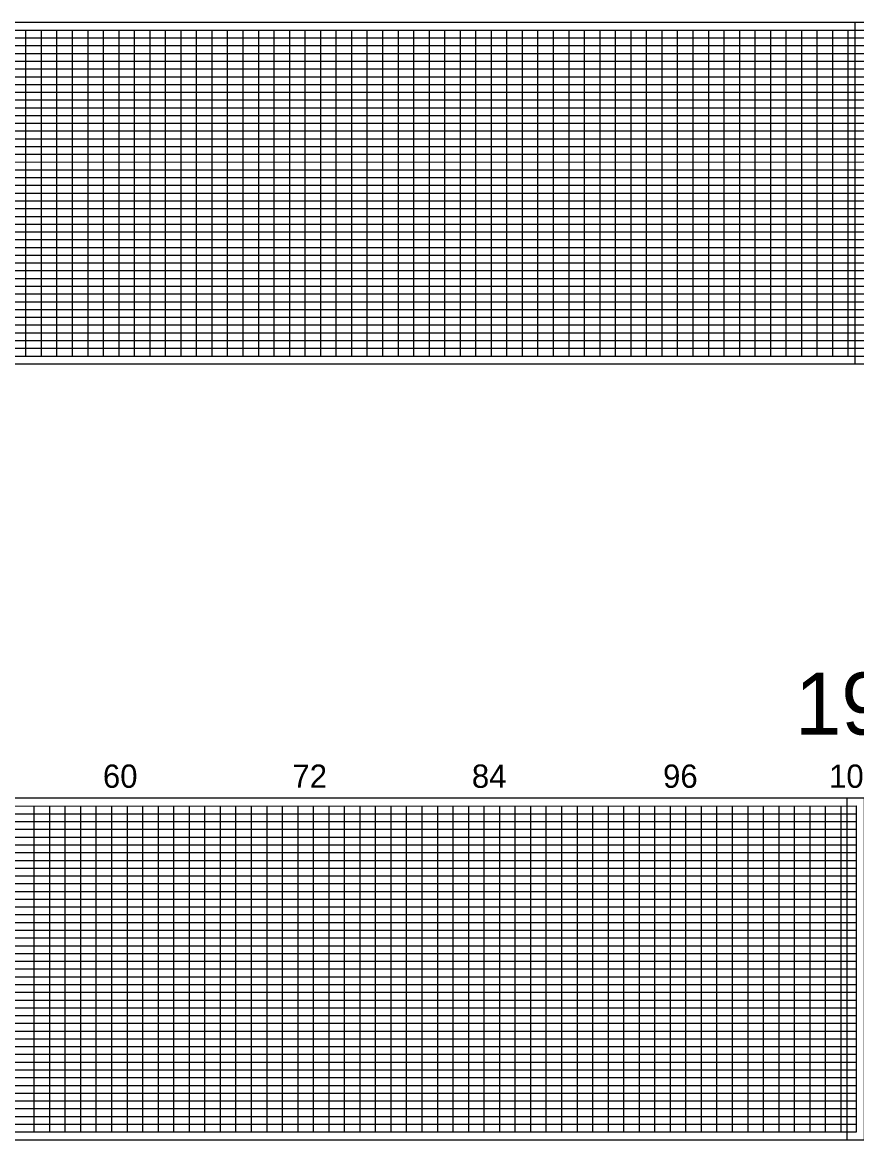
# Model space of a CAD drawing. Extents: x 1914168 to 1925341, y 720939 to 777401.
# Drawn here: x 1917143 to 1919832, y 735939 to 739539 of the extents above; entities that cross this region are included whole.
import ezdxf

# ---------------------------------------------------------------- set-up
doc = ezdxf.new("R2010")
doc.units = 0
for name, color, linetype in [('RD_PD_ALT1_CL', 7, 'Continuous'), ('RD_PD_WallFill', 7, 'Continuous'), ('RD_SHT_IplotShp', 7, 'Continuous')]:
    doc.layers.add(name, color=color, linetype=linetype)

msp = doc.modelspace()

# ---------------------------------------------------------------- linework, layer by layer
at = {"layer": 'RD_PD_WallFill'}
for p, q in [((1914504.9, 739514.1), (1919854.9, 739514.2)), ((1917154.9, 738464.2), (1917154.9, 739514.2)), ((1917204.9, 738464.2), (1917204.9, 739514.2)), ((1917254.9, 738464.2), (1917254.9, 739514.2)), ((1917304.9, 738464.2), (1917304.9, 739514.2)), ((1917354.9, 738464.2), (1917354.9, 739514.2)), ((1917404.9, 738464.2), (1917404.9, 739514.2)), ((1917454.9, 738464.2), (1917454.9, 739514.2)), ((1917504.9, 738464.2), (1917504.9, 739514.2)), ((1917554.9, 738464.2), (1917554.9, 739514.2)), ((1917604.9, 738464.1), (1917604.9, 739514.2)), ((1917654.9, 738464.2), (1917654.9, 739514.2)), ((1917704.9, 738464.2), (1917704.9, 739514.2)), ((1917754.9, 738464.2), (1917754.9, 739514.2)), ((1917804.9, 738464.2), (1917804.9, 739514.2)), ((1917854.9, 738464.2), (1917854.9, 739514.2)), ((1917904.9, 738464.1), (1917904.9, 739514.2)), ((1917954.9, 738464.1), (1917954.9, 739514.2)), ((1918004.9, 738464.2), (1918004.9, 739514.2)), ((1918054.9, 738464.2), (1918054.9, 739514.2)), ((1918104.9, 738464.2), (1918104.9, 739514.2)), ((1918154.9, 738464.2), (1918154.9, 739514.2)), ((1918204.9, 738464.2), (1918204.9, 739514.2)), ((1918254.9, 738464.2), (1918254.9, 739514.2)), ((1918304.9, 738464.2), (1918304.9, 739514.2)), ((1918354.9, 738464.2), (1918354.9, 739514.2)), ((1918404.9, 738464.2), (1918404.9, 739514.2)), ((1918454.9, 738464.2), (1918454.9, 739514.2)), ((1918504.9, 738464.2), (1918504.9, 739514.2)), ((1918554.9, 738464.2), (1918554.9, 739514.2)), ((1918604.9, 738464.2), (1918604.9, 739514.2)), ((1918654.9, 738464.2), (1918654.9, 739514.2)), ((1918704.9, 738464.2), (1918704.9, 739514.2)), ((1918754.9, 738464.2), (1918754.9, 739514.2)), ((1918804.9, 738464.2), (1918804.9, 739514.2)), ((1918854.9, 738464.2), (1918854.9, 739514.2)), ((1918904.9, 738464.2), (1918904.9, 739514.2)), ((1918954.9, 738464.2), (1918954.9, 739514.2)), ((1919004.9, 738464.2), (1919004.9, 739514.2)), ((1919054.9, 738464.2), (1919054.9, 739514.2)), ((1919104.9, 738464.2), (1919104.9, 739514.2)), ((1919154.9, 738464.2), (1919154.9, 739514.2)), ((1919204.9, 738464.2), (1919204.9, 739514.2)), ((1919254.9, 738464.2), (1919254.9, 739514.2)), ((1919304.9, 738464.2), (1919304.9, 739514.2)), ((1919354.9, 738464.2), (1919354.9, 739514.2)), ((1919404.9, 738464.2), (1919404.9, 739514.2)), ((1919454.9, 738464.2), (1919454.9, 739514.2)), ((1919504.9, 738464.2), (1919504.9, 739514.2)), ((1919554.9, 738464.2), (1919554.9, 739514.2)), ((1919604.9, 738464.2), (1919604.9, 739514.2)), ((1919654.9, 738464.2), (1919654.9, 739514.2)), ((1919704.9, 738464.2), (1919704.9, 739514.2)), ((1919754.9, 738464.2), (1919754.9, 739514.2)), ((1919804.9, 738464.2), (1919804.9, 739514.2)), ((1914954.9, 739489.1), (1919854.9, 739489.1)), ((1914954.9, 739464.1), (1919854.9, 739464.1)), ((1914954.9, 739439.1), (1919854.9, 739439.1)), ((1914954.9, 739414.2), (1919854.9, 739414.1)), ((1914954.9, 739389.1), (1919854.9, 739389.2)), ((1914504.9, 739364.1), (1919854.9, 739364.1)), ((1914504.9, 739339.1), (1919854.9, 739339.1)), ((1914504.9, 739314.1), (1919854.9, 739314.2)), ((1914504.9, 739289.2), (1919854.9, 739289.1)), ((1914504.9, 739264.2), (1919854.9, 739264.2)), ((1914504.9, 739239.1), (1919854.9, 739239.1)), ((1914504.9, 739214.1), (1919854.9, 739214.1)), ((1914504.9, 739189.2), (1919854.9, 739189.1)), ((1914504.9, 739164.1), (1919854.9, 739164.1)), ((1914504.9, 739139.2), (1919854.9, 739139.1)), ((1914504.9, 739114.1), (1919854.9, 739114.1)), ((1914504.9, 739089.1), (1919854.9, 739089.2)), ((1914504.9, 739064.1), (1919854.9, 739064.1)), ((1914504.9, 739039.1), (1919854.9, 739039.2)), ((1914504.9, 739014.1), (1919854.9, 739014.1)), ((1914504.9, 738989.1), (1919854.9, 738989.1)), ((1914504.9, 738964.2), (1919854.9, 738964.1)), ((1914504.9, 738939.1), (1919854.9, 738939.1)), ((1914504.9, 738914.1), (1919854.9, 738914.1)), ((1914504.9, 738889.1), (1919854.9, 738889.1)), ((1914504.9, 738864.1), (1919854.9, 738864.2)), ((1914504.9, 738839.1), (1919854.9, 738839.1)), ((1914504.9, 738814.1), (1919854.9, 738814.1)), ((1914504.9, 738789.1), (1919854.9, 738789.1)), ((1914504.9, 738764.1), (1919854.9, 738764.1)), ((1914504.9, 738739.1), (1919854.9, 738739.1)), ((1914504.9, 738714.1), (1919854.9, 738714.1)), ((1914504.9, 738689.1), (1919854.9, 738689.1)), ((1914504.9, 738664.1), (1919854.9, 738664.1)), ((1914504.9, 738639.1), (1919854.9, 738639.1)), ((1914504.9, 738614.1), (1919854.9, 738614.1)), ((1914504.9, 738589.1), (1919854.9, 738589.1)), ((1914504.9, 738564.1), (1919854.9, 738564.1)), ((1914504.9, 738539.1), (1919854.9, 738539.1)), ((1914504.9, 738514.1), (1919854.9, 738514.1)), ((1914554.9, 738489.1), (1919854.9, 738489.1)), ((1914504.9, 738464.1), (1919854.9, 738464.1)), ((1914481.7, 737014.1), (1919831.7, 737014.2)), ((1917181.7, 735964.2), (1917181.7, 737014.2)), ((1917231.7, 735964.2), (1917231.7, 737014.2)), ((1917281.7, 735964.2), (1917281.7, 737014.2)), ((1917331.7, 735964.2), (1917331.7, 737014.2)), ((1917381.7, 735964.2), (1917381.7, 737014.2)), ((1917431.7, 735964.2), (1917431.7, 737014.2)), ((1917481.7, 735964.2), (1917481.7, 737014.2)), ((1917531.7, 735964.2), (1917531.7, 737014.2)), ((1917581.7, 735964.1), (1917581.7, 737014.2)), ((1917631.7, 735964.2), (1917631.7, 737014.2)), ((1917681.7, 735964.2), (1917681.7, 737014.2)), ((1917731.7, 735964.2), (1917731.7, 737014.2)), ((1917781.7, 735964.2), (1917781.7, 737014.2)), ((1917831.7, 735964.2), (1917831.7, 737014.2)), ((1917881.7, 735964.1), (1917881.7, 737014.2)), ((1917931.7, 735964.1), (1917931.7, 737014.2)), ((1917981.7, 735964.2), (1917981.7, 737014.2)), ((1918031.7, 735964.2), (1918031.7, 737014.2)), ((1918081.7, 735964.2), (1918081.7, 737014.2)), ((1918131.7, 735964.2), (1918131.7, 737014.2)), ((1918181.7, 735964.2), (1918181.7, 737014.2)), ((1918231.7, 735964.2), (1918231.7, 737014.2)), ((1918281.7, 735964.2), (1918281.7, 737014.2)), ((1918331.7, 735964.2), (1918331.7, 737014.2)), ((1918381.7, 735964.2), (1918381.7, 737014.2)), ((1918431.7, 735964.2), (1918431.7, 737014.2)), ((1918481.7, 735964.2), (1918481.7, 737014.2)), ((1918531.7, 735964.2), (1918531.7, 737014.2)), ((1918581.7, 735964.2), (1918581.7, 737014.2)), ((1918631.7, 735964.2), (1918631.7, 737014.2)), ((1918681.7, 735964.2), (1918681.7, 737014.2)), ((1918731.7, 735964.2), (1918731.7, 737014.2)), ((1918781.7, 735964.2), (1918781.7, 737014.2)), ((1918831.7, 735964.2), (1918831.7, 737014.2)), ((1918881.7, 735964.2), (1918881.7, 737014.2)), ((1918931.7, 735964.2), (1918931.7, 737014.2)), ((1918981.7, 735964.2), (1918981.7, 737014.2)), ((1919031.7, 735964.2), (1919031.7, 737014.2)), ((1919081.7, 735964.2), (1919081.7, 737014.2)), ((1919131.7, 735964.2), (1919131.7, 737014.2)), ((1919181.7, 735964.2), (1919181.7, 737014.2)), ((1919231.7, 735964.2), (1919231.7, 737014.2)), ((1919281.7, 735964.2), (1919281.7, 737014.2)), ((1919331.7, 735964.2), (1919331.7, 737014.2)), ((1919381.7, 735964.2), (1919381.7, 737014.2)), ((1919431.7, 735964.2), (1919431.7, 737014.2)), ((1919481.7, 735964.2), (1919481.7, 737014.2)), ((1919531.7, 735964.2), (1919531.7, 737014.2)), ((1919581.7, 735964.2), (1919581.7, 737014.2)), ((1919631.7, 735964.2), (1919631.7, 737014.2)), ((1919681.7, 735964.2), (1919681.7, 737014.2)), ((1919731.7, 735964.2), (1919731.7, 737014.2)), ((1919781.7, 735964.2), (1919781.7, 737014.2)), ((1919831.7, 735964.2), (1919831.7, 737014.2)), ((1914931.7, 736989.1), (1919831.7, 736989.1)), ((1914931.7, 736964.1), (1919831.7, 736964.1)), ((1914931.7, 736939.1), (1919831.7, 736939.1)), ((1914931.7, 736914.2), (1919831.7, 736914.1)), ((1914931.7, 736889.1), (1919831.7, 736889.2)), ((1914481.7, 736864.1), (1919831.7, 736864.1)), ((1914481.7, 736839.1), (1919831.7, 736839.1)), ((1914481.7, 736814.1), (1919831.7, 736814.2)), ((1914481.7, 736789.2), (1919831.7, 736789.1)), ((1914481.7, 736764.2), (1919831.7, 736764.2)), ((1914481.7, 736739.1), (1919831.7, 736739.1)), ((1914481.7, 736714.1), (1919831.7, 736714.1)), ((1914481.7, 736689.2), (1919831.7, 736689.1)), ((1914481.7, 736664.1), (1919831.7, 736664.1)), ((1914481.7, 736639.2), (1919831.7, 736639.1)), ((1914481.7, 736614.1), (1919831.7, 736614.1)), ((1914481.7, 736589.1), (1919831.7, 736589.2)), ((1914481.7, 736564.1), (1919831.7, 736564.1)), ((1914481.7, 736539.1), (1919831.7, 736539.2)), ((1914481.7, 736514.1), (1919831.7, 736514.1)), ((1914481.7, 736489.1), (1919831.7, 736489.1)), ((1914481.7, 736464.2), (1919831.7, 736464.1)), ((1914481.7, 736439.1), (1919831.7, 736439.1)), ((1914481.7, 736414.1), (1919831.7, 736414.1)), ((1914481.7, 736389.1), (1919831.7, 736389.1)), ((1914481.7, 736364.1), (1919831.7, 736364.2)), ((1914481.7, 736339.1), (1919831.7, 736339.1)), ((1914481.7, 736314.1), (1919831.7, 736314.1)), ((1914481.7, 736289.1), (1919831.7, 736289.1)), ((1914481.7, 736264.1), (1919831.7, 736264.1)), ((1914481.7, 736239.1), (1919831.7, 736239.1)), ((1914481.7, 736214.1), (1919831.7, 736214.1)), ((1914481.7, 736189.1), (1919831.7, 736189.1)), ((1914481.7, 736164.1), (1919831.7, 736164.1)), ((1914481.7, 736139.1), (1919831.7, 736139.1)), ((1914481.7, 736114.1), (1919831.7, 736114.1)), ((1914481.7, 736089.1), (1919831.7, 736089.1)), ((1914481.7, 736064.1), (1919831.7, 736064.1)), ((1914481.7, 736039.1), (1919831.7, 736039.1)), ((1914481.7, 736014.1), (1919831.7, 736014.1)), ((1914531.7, 735989.1), (1919831.7, 735989.1)), ((1914481.7, 735964.1), (1919831.7, 735964.1))]:
    msp.add_line(p, q, dxfattribs=at)
at = {"layer": 'RD_SHT_IplotShp'}
for points in [[(1914479.9, 738439.1), (1919879.9, 738439.1), (1919879.9, 739539.1), (1914479.9, 739539.1)], [(1919825.9, 738439.1), (1925225.9, 738439.1), (1925225.9, 739539.1), (1919825.9, 739539.1)], [(1914456.7, 735939.1), (1919856.7, 735939.1), (1919856.7, 737039.1), (1914456.7, 737039.1)], [(1919800.4, 735939.1), (1924000.4, 735939.1), (1924000.4, 737039.1), (1919800.4, 737039.1)]]:
    msp.add_lwpolyline(points, close=True, dxfattribs=at)

# ---------------------------------------------------------------- texts
at = {"layer": 'RD_PD_ALT1_CL'}
msp.add_text('19', height=200, dxfattribs=at).set_placement((1919633.6, 737244.2))
at = {"layer": 'RD_PD_WallFill'}
for s, p in [('60', (1917402.9, 737072.8)), ('72', (1918013.5, 737072.8)), ('84', (1918591.8, 737072.8)), ('96', (1919207.9, 737072.8)), ('108', (1919742.9, 737072.8))]:
    msp.add_text(s, height=75, dxfattribs=at).set_placement(p)

doc.saveas('drawing.dxf')
